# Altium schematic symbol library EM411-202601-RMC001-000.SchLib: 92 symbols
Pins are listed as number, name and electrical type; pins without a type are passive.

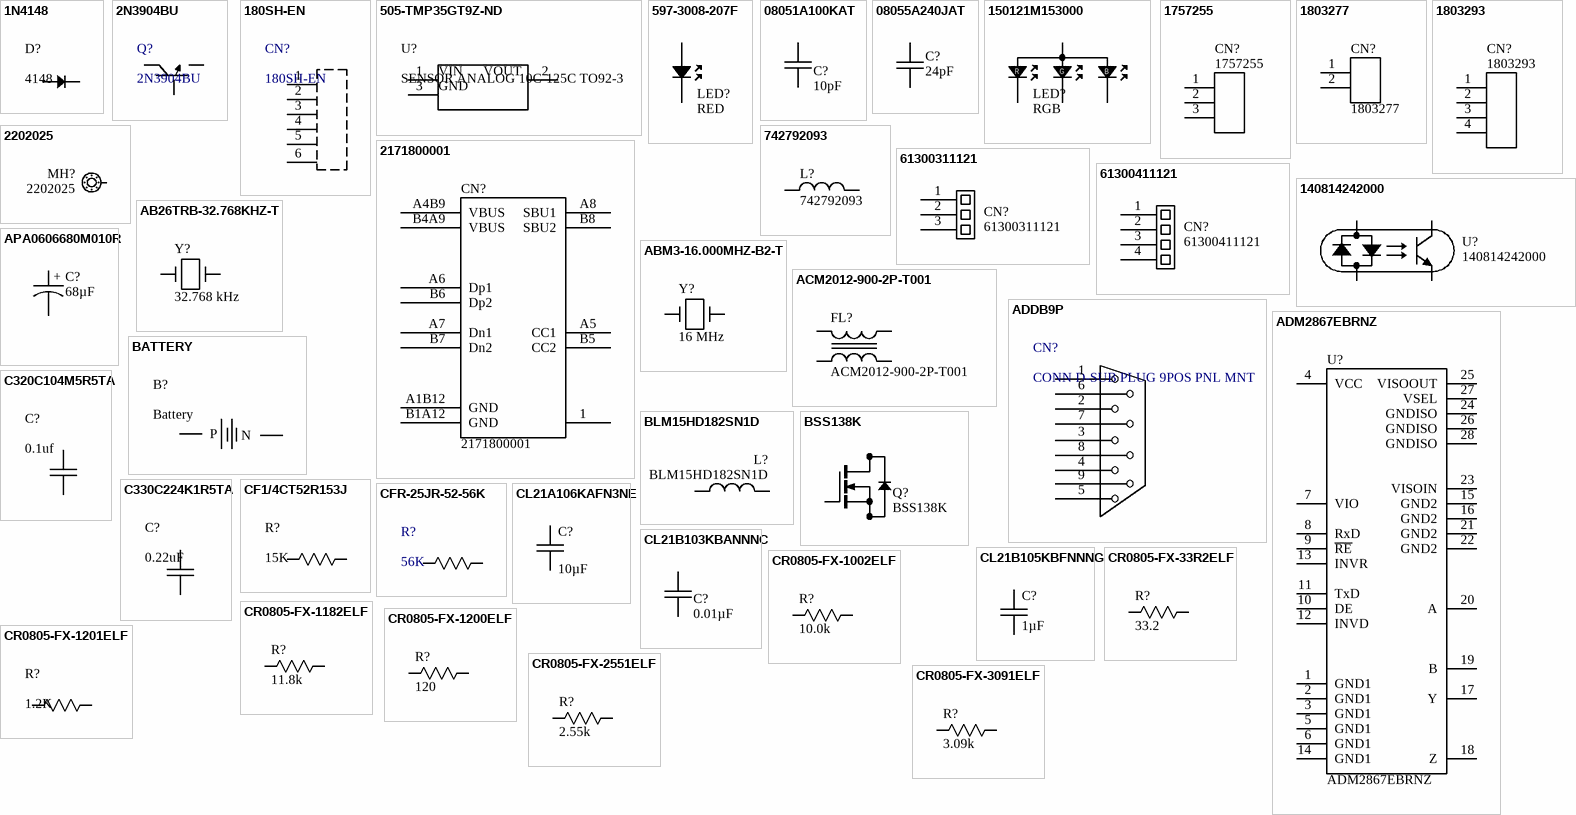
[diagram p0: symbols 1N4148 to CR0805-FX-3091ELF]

## 1N4148
designator D?, comment 4148
Diode 100 V 200mA Through Hole DO-35
footprint LED
pins: 1 A, 2 C

## 2N3904BU
designator Q?
Bipolar (BJT) Transistor NPN 40 V 200 mA 300MHz 625 mW Through Hole TO-92-3
pins: 1, 2, 3

## 180SH-EN
designator CN?
pins: 1, 2 3, 3 5, 4 7, 5 9, 6 9

## 505-TMP35GT9Z-ND
designator U?, comment SENSOR ANALOG 10C-125C TO92-3
Temperature Sensor Analog, Local 10°C ~ 125°C 10mV/°C TO-92-3
pins: 1, 2, 3

## 597-3008-207F
designator LED?, comment RED
Micro LED, 597 Series, Red, SMD LED; PartNumber: 597-3008-207F; Manufacturer: Dialight Corporation
footprint LEDM3228X19N (Molded LED, 2-Leads, Body 3.20x2.80mm, IPC Medium Density)
pins: A, K

## 08051A100KAT
designator C?, comment 10pF
10pF/100V/±10% C0G (NP0) Ceramic Chip Capacitor; Manufacturer: Kyocera/AVX; PartNumber: 08051A100KAT
footprint CAPC2012X09N (Chip Capacitor, 2-Leads, Body 2.00x1.25mm, IPC Medium Density)
pins: 1, 2
1 alternate drawing of the same symbol

## 08055A240JAT
designator C?, comment 24pF
24pF/50V/±5% C0G (NP0) Ceramic Chip Capacitor; Manufacturer: Kyocera/AVX; PartNumber: 08055A240JAT
footprint CAPC2012X09N (Chip Capacitor, 2-Leads, Body 2.00x1.25mm, IPC Medium Density)
pins: 1, 2
1 alternate drawing of the same symbol

## 150121M153000
designator LED?, comment RGB
Micro RGB SMD LED, Common Anode; PartNumber: 150121M153000; Manufacturer: Wurth Elektronik
footprint WURTH_150121M153000
pins: 1 R, 2 G, 3 B, 4 A

## 1757255
designator CN?
MSTBA 2,5/3-G-5,08 Pluggable Terminal Block 3 Pos 5.08mm pitch Through Hole Header; Manufacturer: Phoenix Contact
footprint PHOENIX_1757255 (PCB header - MSTBA 2,5/ 3-G-5,08)
pins: 1, 2, 3

## 1803277
designator CN?
MC 1,5/2G-3,81 Pluggable Terminal Block 2 Pos 3.81mm pitch Through Hole Header; Manufacturer: Phoenix Contact
footprint PHOENIX_1803277 (PCB Header - MC 1,5/ 2-G-3,81)
pins: 1, 2

## 1803293
designator CN?
MC 1,5/4G-3,81 Pluggable Terminal Block 4 Pos 3.81mm pitch Through Hole Header; Manufacturer: Phoenix Contact
footprint PHOENIX_1803293 (PCB header - MC 1,5/ 4-G-3,81)
pins: 1, 2, 3, 4
1 alternate drawing of the same symbol

## 2202025
designator MH?
UM-BASIC/PRO PE CONTACT L1; Manufacturer: Phoenix Contact
footprint PHOENIX_2202025 (PE Contact Level 1)
pins: 0

## 742792093
designator L?
Multilayer SMD Ferrite; Manufacturer: Wurth Elektronik
footprint INDC2012X11N (Chip Inductor, 2-Leads, Body 2.00x1.20mm, IPC Medium Density)
pins: 1, 2

## 2171800001
designator CN?
USB-C Receptacle, Right-Angle, Surface Mount, Top Mount, Center Height 5.9mm, Single Row, 16 Circuits; Manufacturer: Molex
footprint MOLEX_2171800001
pins: 1 SHELL, A1B12 GND, A4B9 VBUS, A5 CC1, A6 Dp1, A7 Dn1, A8 SBU1, B1A12 GND, B4A9 VBUS, B5 CC2, B6 Dp2, B7 Dn2, B8 SBU2

## 61300311121
designator CN?
Connector Header Through Hole 3 position 0.100" (2.54mm); Manufacturer: Wurth Elektronik
footprint WURTH_61300311121
pins: 1, 2, 3
3 alternate drawings of the same symbol

## 61300411121
designator CN?
Connector Header Through Hole 4 position 0.100" (2.54mm); Manufacturer: Wurth Elektronik
footprint WURTH_61300411121
pins: 1, 2, 3, 4
2 alternate drawings of the same symbol

## 140814242000
designator U?
WL-OCPT Optocoupler Phototransistor; Manufacturer: Wurth Elektronik
footprint WURTH_140814242000 (Optocoupler Phototransistor, body 6.5x4.58mm)
pins: 1 A, 2 K, 3 E, 4 C

## AB26TRB-32.768KHZ-T
designator Y?, comment 32.768 kHz
32.768 kHz Radial Can Crystal; PartNumber: AB26TRB-32.768KHZ-T; Manufacturer: Abracon Corporation
footprint ABRACON_AB26TRB (Low Frequency Reflowable Cylindrical Watch Crystal)
pins: 1, 2

## ABM3-16.000MHZ-B2-T
designator Y?, comment 16 MHz
16 MHz Miniature Ceramic SMD Crystal; PartNumber: ABM3-16.000MHZ-B2-T; Manufacturer: Abracon Corporation
footprint ABRACON_ABM3 (Ceramic SMD Crystal)
pins: 1, 2

## ACM2012-900-2P-T001
designator FL?
Common Mode Filter; Manufacturer: TDK
footprint LITTELFUSE_ACM2012-900-2P-T001 (Common Mode Choke)
pins: 1, 2, 3, 4

## ADDB9P
designator CN?, comment CONN D-SUB PLUG 9POS PNL MNT
9 Position D-Sub Plug, Male Pins Connector
pins: 1, 2, 3 1, 4 1, 5 1, 6 1, 7 1, 8 1, 9 1

## ADM2867EBRNZ
designator U?
5.7 kV RMS Signal and Power Isolated RS-485 Transceiver with ±15 kV IEC ESD; Manufacturer: Analog Devices, Inc.
footprint SOP65P1030X265-28N (SOP, 28-Leads, Body 10.30x7.50mm, Pitch 0.65mm, IPC Medium Density)
pins: 1 GND1 (power), 2 GND1 (power), 3 GND1 (power), 4 VCC, 5 GND1 (power), 6 GND1 (power), 7 VIO, 8 RxD, 9 ~{RE}, 10 DE, 11 TxD, 12 INVD, 13 INVR, 14 GND1 (power), 15 GND2, 16 GND2, 17 Y, 18 Z, 19 B, 20 A, 21 GND2, 22 GND2, 23 VISOIN, 24 GNDISO, 25 VISOOUT, 26 GNDISO, 27 VSEL, 28 GNDISO

## APA0606680M010R
designator C?, comment 68µF
68µF/10V/20% SMD Aluminum Conductive Polymer Electrolytic Capacitor; Manufacturer: AVX; PartNumber: APA0606680M010R
footprint CAPAE7366X65M (Aluminum Electrolytic Capacitor, Body 6.60x6.60x6.50mm, IPC Low Density)
pins: 1, 2

## BATTERY
designator B?, comment Battery
pins: 1 P, 2 N

## BLM15HD182SN1D
designator L?
GHz Noise Suppression Chip Ferrite Bead; Manufacturer: Murata Electronics
footprint INDC1005X06N (Chip Inductor, 2-Leads, Body 1.00x0.50mm, IPC Medium Density)
pins: 1, 2

## BSS138K
designator Q?
N-Channel Logic Level Enhancement Mode Field Effect Transistor; Manufacturer: Onsemi
footprint SOT95P237X111-3N (SOT23, 3-Leads, Body 2.92x2.37mm, Pitch 0.95mm, IPC Medium Density)
pins: 1 G "Gate", 2 S "Source", 3 D "Drain"

## C320C104M5R5TA
designator C?, comment 0.1uf
0.1 µF ±20% 50V Ceramic Capacitor X7R Radial
pins: 1, 2

## C330C224K1R5TA
designator C?, comment 0.22uF
0.22 µF ±10% 100V Ceramic Capacitor X7R Radial
footprint C330C224K1R5TA (0.22 µF ±10% 100V Ceramic Capacitor X7R Radial)
pins: 1, 2

## CF1/4CT52R153J
designator R?, comment 15K
15 kOhms ±5% 0.25W, 1/4W Through Hole Resistor Axial Carbon Film
pins: 1, 2

## CFR-25JR-52-56K
designator R?, comment 56K
56 kOhms ±5% 0.25W, 1/4W Through Hole Resistor Axial Automotive AEC-Q200 Carbon Film
pins: 1, 2

## CL21A106KAFN3NE
designator C?, comment 10µF
10µF/25V 10% X5R Multi-Layer Ceramic Capacitor; Manufacturer: Samsung Electro-Mechanics; PartNumber: CL21A106KAFN3NE
footprint CAPC2012X14N (Chip Capacitor, 2-Leads, Body 2.00x1.25mm, IPC Medium Density)
pins: 1, 2

## CL21B103KBANNNC
designator C?, comment 0.01µF
0.01µF/50V/±10% X7R Ceramic Chip Capacitor; Manufacturer: Samsung Electro-Mechanics; PartNumber: CL21B103KBANNNC
footprint CAPC2012X08N (Chip Capacitor, 2-Leads, Body 2.00x1.25mm, IPC Medium Density)
pins: 1, 2
1 alternate drawing of the same symbol

## CL21B105KBFNNNG
designator C?, comment 1µF
1µF/50V/±10% X7R Ceramic Chip Capacitor; Manufacturer: Samsung Electro-Mechanics; PartNumber: CL21B105KBFNNNG
footprint CAPC2012X14N (Chip Capacitor, 2-Leads, Body 2.00x1.25mm, IPC Medium Density)
pins: 1, 2
1 alternate drawing of the same symbol

## CR0805-FX-33R2ELF
designator R?, comment 33.2
33.2, 1%, 0.125W Thick Film Chip Resistor; Manufacturer: Bourns; PartNumber: CR0805-FX-33R2ELF
footprint RESC2012X06N (Chip Resistor, 2-Leads, Body 2.00x1.25mm, IPC Medium Density)
pins: 1, 2

## CR0805-FX-1002ELF
designator R?, comment 10.0k
10.0k, 1%, 0.125W Thick Film Chip Resistor; Manufacturer: Bourns; PartNumber: CR0805-FX-1002ELF
footprint RESC2012X06N (Chip Resistor, 2-Leads, Body 2.00x1.25mm, IPC Medium Density)
pins: 1, 2

## CR0805-FX-1182ELF
designator R?, comment 11.8k
11.8k, 1%, 0.125W Thick Film Chip Resistor; Manufacturer: Bourns; PartNumber: CR0805-FX-1182ELF
footprint RESC2012X06N (Chip Resistor, 2-Leads, Body 2.00x1.25mm, IPC Medium Density)
pins: 1, 2

## CR0805-FX-1200ELF
designator R?, comment 120
120, 1%, 0.125W Thick Film Chip Resistor; Manufacturer: Bourns; PartNumber: CR0805-FX-1200ELF
footprint RESC2012X06N (Chip Resistor, 2-Leads, Body 2.00x1.25mm, IPC Medium Density)
pins: 1, 2

## CR0805-FX-1201ELF
designator R?, comment 1.2K
1.2 kOhms ±1% 0.125W, 1/8W Chip Resistor 0805 (2012 Metric) Moisture Resistant Thick Film
footprint RESC2012X06N (Chip Resistor, 2-Leads, Body 2.00x1.25mm, IPC Medium Density)
pins: 1, 2

## CR0805-FX-2551ELF
designator R?, comment 2.55k
2.55k, 1%, 0.125W Thick Film Chip Resistor; Manufacturer: Bourns; PartNumber: CR0805-FX-2551ELF
footprint RESC2012X06N (Chip Resistor, 2-Leads, Body 2.00x1.25mm, IPC Medium Density)
pins: 1, 2

## CR0805-FX-3091ELF
designator R?, comment 3.09k
3.09k, 1%, 0.125W Thick Film Chip Resistor; Manufacturer: Bourns; PartNumber: CR0805-FX-3091ELF
footprint RESC2012X06N (Chip Resistor, 2-Leads, Body 2.00x1.25mm, IPC Medium Density)
pins: 1, 2

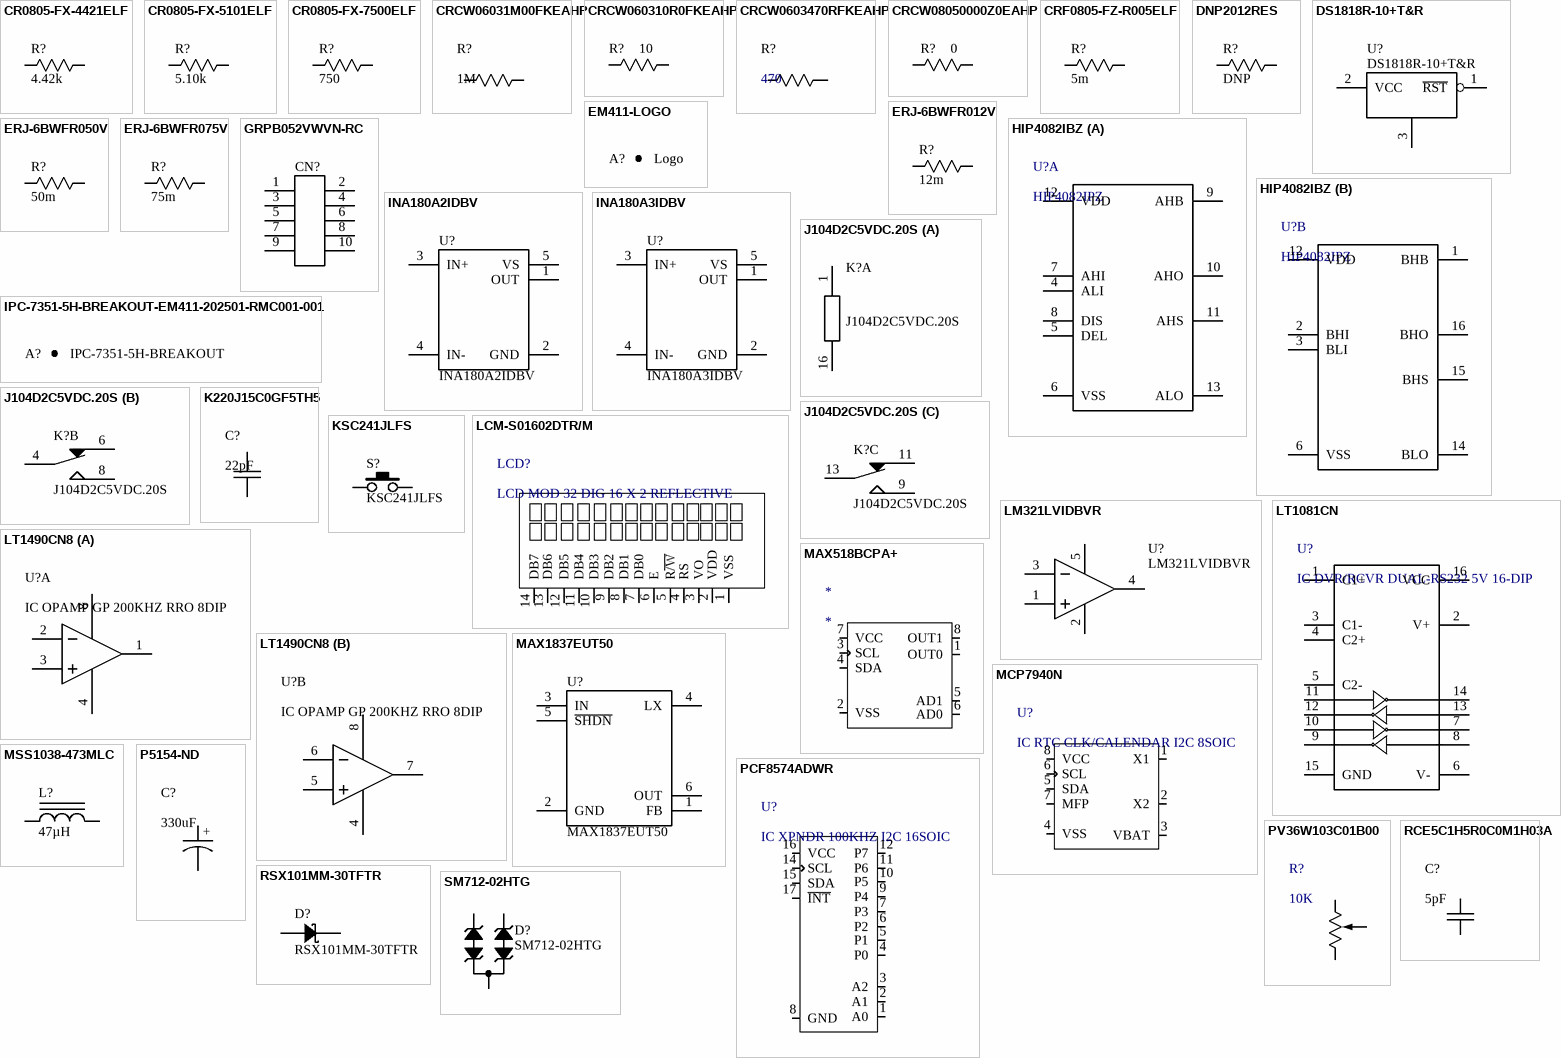
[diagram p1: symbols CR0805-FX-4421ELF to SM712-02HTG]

## CR0805-FX-4421ELF
designator R?, comment 4.42k
4.42k, 1%, 0.125W Thick Film Chip Resistor; Manufacturer: Bourns; PartNumber: CR0805-FX-4421ELF
footprint RESC2012X06N (Chip Resistor, 2-Leads, Body 2.00x1.25mm, IPC Medium Density)
pins: 1, 2

## CR0805-FX-5101ELF
designator R?, comment 5.10k
5.10k, 1%, 0.125W Thick Film Chip Resistor; Manufacturer: Bourns; PartNumber: CR0805-FX-5101ELF
footprint RESC2012X06N (Chip Resistor, 2-Leads, Body 2.00x1.25mm, IPC Medium Density)
pins: 1, 2

## CR0805-FX-7500ELF
designator R?, comment 750
750, 1%, 0.125W Thick Film Chip Resistor; Manufacturer: Bourns; PartNumber: CR0805-FX-7500ELF
footprint RESC2012X06N (Chip Resistor, 2-Leads, Body 2.00x1.25mm, IPC Medium Density)
pins: 1, 2

## CRCW06031M00FKEAHP
designator R?, comment 1M
1 MOhms ±1% 0.333W, 1/3W Chip Resistor 0603 (1608 Metric) Automotive AEC-Q200, Pulse Withstanding Thick Film
pins: 1, 2

## CRCW060310R0FKEAHP
designator R?, comment 10
10, 1%, 0.33W Pulse Proof, High Power Thick Film Chip Resistor; Manufacturer: Vishay Intertechnology; PartNumber: CRCW060310R0FKEAHP
footprint RESC1608X06N (Chip Resistor, 2-Leads, Body 1.60x0.85mm, IPC Medium Density)
pins: 1, 2

## CRCW0603470RFKEAHP
designator R?, comment 470
470 Ohms ±1% 0.333W, 1/3W Chip Resistor 0603 (1608 Metric) Automotive AEC-Q200, Pulse Withstanding Thick Film
pins: 1, 2

## CRCW08050000Z0EAHP
designator R?, comment 0
0, Jumper, Pulse Proof, High Power Thick Film Chip Resistor; Manufacturer: Vishay Intertechnology; PartNumber: CRCW08050000Z0EAHP
footprint VISHAY_RESC2012X06N (Chip Resistor, 2-Leads, Body 2.00x1.25mm, IPC Medium Density)
pins: 1, 2

## CRF0805-FZ-R005ELF
designator R?, comment 5m
5m, 1%, 0.5W Thick Film Chip Resistor; Manufacturer: Bourns; PartNumber: CRF0805-FZ-R005ELF
footprint RESC2012X08N (Chip Resistor, 2-Leads, Body 2.00x1.25mm, IPC Medium Density)
pins: 1, 2

## DNP2012RES
designator R?, comment DNP  (no BOM)
Placeholder for 2012 Resistor; Manufacturer: Confederation College; PartNumber: DNP2012RES
footprint RESC2012X06N (Chip Resistor, 2-Leads, Body 2.00x1.25mm, IPC Medium Density)
pins: 1, 2

## DS1818R-10+T&R
designator U?
3.3 V EconoReset with Pushbutton; Manufacturer: Maxim Integrated
footprint SOT95P237X112-3N (SOT23, 3-Leads, Body 2.92x2.37mm, Pitch 0.95mm, IPC Medium Density)
pins: 1 ~{RST} (oc), 2 VCC (power), 3 GND (power)

## EM411-LOGO
designator A?, comment Logo  (no BOM)
footprint EM411-LOGO (Confederation College Logo)

## ERJ-6BWFR012V
designator R?, comment 12m
12m, 1%, 0.5W Thick Film Chip Resistor; Manufacturer: Panasonic; PartNumber: ERJ-6BWFR012V
footprint RESC2012X08N (Chip Resistor, 2-Leads, Body 2.00x1.25mm, IPC Medium Density)
pins: 1, 2

## ERJ-6BWFR050V
designator R?, comment 50m
50m, 1%, 0.5W Thick Film Chip Resistor; Manufacturer: Panasonic; PartNumber: ERJ-6BWFR050V
footprint RESC2012X08N (Chip Resistor, 2-Leads, Body 2.00x1.25mm, IPC Medium Density)
pins: 1, 2

## ERJ-6BWFR075V
designator R?, comment 75m
75m, 1%, 0.5W Thick Film Chip Resistor; Manufacturer: Panasonic; PartNumber: ERJ-6BWFR075V
footprint RESC2012X08N (Chip Resistor, 2-Leads, Body 2.00x1.25mm, IPC Medium Density)
pins: 1, 2

## GRPB052VWVN-RC
designator CN?  (value not drawn)
.050"[1.27mm] Contact Centers, Male Header; Manufacturer: Sullins Connector Solutions, Inc.
footprint SULLINS_GRPB052VWVN-RC (CONN HEADER VERT 10POS 1.27MM)
pins: 1, 2, 3, 4, 5, 6, 7, 8, 9, 10

## HIP4082IBZ
designator U?, comment HIP4082IPZ
Half Bridge, Full Bridge Driver DC Motors, General Purpose N-Channel MOSFET 16-SOIC
part A pins: 4 ALI, 5 DEL, 6 VSS, 7 AHI, 8 DIS, 9 AHB, 10 AHO, 11 AHS, 12 VDD, 13 ALO
part B pins: 1 BHB, 2 BHI, 3 BLI, 6 VSS, 12 VDD, 14 BLO, 15 BHS, 16 BHO

## INA180A2IDBV
designator U?
Voltage Output, Current-Sense Amplifiers, Gain 50; Manufacturer: Texas Instruments
footprint SOT95P280X145-5N (SOT23, 5-Leads, Body 2.90x2.80mm, Pitch 0.95mm, IPC Medium Density)
pins: 1 OUT, 2 GND, 3 IN+, 4 IN-, 5 VS

## INA180A3IDBV
designator U?
Voltage Output, Current-Sense Amplifiers, Gain 100; Manufacturer: Texas Instruments
footprint SOT95P280X145-5N (SOT23, 5-Leads, Body 2.90x2.80mm, Pitch 0.95mm, IPC Medium Density)
pins: 1 OUT, 2 GND, 3 IN+, 4 IN-, 5 VS

## IPC-7351-5H-BREAKOUT-EM411-202501-RMC001-001
designator A?, comment IPC-7351-5H-BREAKOUT  (no BOM)
IPC-7351-5H-BREAKOUT for EM411-202501-RMC001-001
footprint IPC-7351-5H-BREAKOUT-EM411-202501-RMC001-001 (IPC-7351 Breakout for EM411-202401-RMC001-001)

## J104D2C5VDC.20S
designator K?
J104D Series Dual Form C 5V, 2A PCB Relay; Manufacturer: Circuit Interrupter Technology
footprint CIT_J104D (Dual Form C Signal Relay)
part A pins: 1, 16
part B pins: 4, 6, 8
part C pins: 9, 11, 13
1 alternate drawing of the same symbol

## K220J15C0GF5TH5
designator C?, comment 22pF
22 pF ±5% 50V Ceramic Capacitor C0G, NP0 Radial
footprint K220J15C0GF5TH5
pins: 1, 2

## KSC241JLFS
designator S?
KSC Series Sealed Tact Switch for SMT; Manufacturer: C&K Components
footprint CK_KSC241JLFS (KSC2 Series Sealed Tact Switch for SMT)
pins: 1, 2

## LCM-S01602DTR/M
designator LCD?, comment LCD MOD 32 DIG 16 X 2 REFLECTIVE
Character Display Module Reflective 5 x 8 Dots TN - Twisted Nematic Without Backlight Parallel 66.00mm x 26.00mm x 6.50mm
pins: 1 VSS, 2 VDD, 3 VO, 4 RS, 5 R~{/W}, 6 E, 7 DB0, 8 DB1, 9 DB2, 10 DB3, 11 DB4, 12 DB5, 13 DB6, 14 DB7

## LM321LVIDBVR
designator U?
Industry Standard, Low Voltage Operational Amplifier; Manufacturer: Texas Instruments
footprint SOT95P280X145-5N (SOT23, 5-Leads, Body 2.90x2.80mm, Pitch 0.95mm, IPC Medium Density)
pins: 1 IN+, 2 V- (power), 3 IN-, 4 OUT, 5 V+ (power)

## LT1081CN
designator U?, comment IC DVR/RCVR DUAL-RS232 5V 16-DIP
2/2 Transceiver Full RS232 16-PDIP
pins: 1 C1+, 2 V+, 3 C1-, 4 C2+, 5 C2-, 6 V-, 7 C2-, 8 C2-, 9 C2-, 10 C2-, 11 C2-, 12 C2-, 13 C2-, 14 C2-, 15 GND, 16 VCC

## LT1490CN8
designator U?, comment IC OPAMP GP 200KHZ RRO 8DIP
Standard (General Purpose) Amplifier 2 Circuit Rail-to-Rail 8-PDIP
part A pins: 1 9, 2 IN-, 3 IN+, 4 V- (power), 8 V+ (power)
part B pins: 4 V- (power), 5 IN+, 6 IN-, 7, 8 V+ (power)

## MAX518BCPA+
designator *
pins: 1 OUT0, 2 VSS, 3 SCL, 4 SDA, 5 AD1, 6 AD0, 7 VCC, 8 OUT1

## MAX1837EUT50
designator U?
24V Internal Switch, 100% Duty Cycle, Step-Down Converter; Manufacturer: Maxim Integrated
footprint SOT95P280X145-6N (SOT23, 6-Leads, Body 2.90x2.80mm, Pitch 0.95mm, IPC Medium Density)
pins: 1 FB, 2 GND, 3 IN, 4 LX, 5 ~{SHDN}, 6 OUT

## MCP7940N
designator U?, comment IC RTC CLK/CALENDAR I2C 8SOIC
Real Time Clock (RTC) IC Clock/Calendar 64B I2C, 2-Wire Serial 8-SOIC (0.154", 3.90mm Width)
pins: 1 X1, 2 X2, 3 VBAT, 4 VSS, 5 SDA, 6 SCL, 7 MFP, 8 VCC

## MSS1038-473MLC
designator L?, comment 47µH
47µH Shielded Power Inductor; PartNumber: MSS1038-473MLC; Manufacturer: Coilcraft
footprint INDP102102X40N (Precision Wire Wound Inductor, 2-Leads, Body 10.20x10.15mm, IPC Medium Density)
pins: 1, 2

## P5154-ND
designator C?, comment 330uF
330 µF 25 V Aluminum Electrolytic Capacitors Radial, Can 2000 Hrs @ 85°C
footprint PCAP_8x112_PAN
pins: 1, 2

## PCF8574ADWR
designator U?, comment IC XPNDR 100KHZ I2C 16SOIC
I/O Expander 8 I2C 100 kHz 16-SOIC
pins: 1 A0, 2 A1, 3 A2, 4 P0, 5 P1, 6 P2, 7 P3, 8 GND, 9 P4, 10 P5, 11 P6, 12 P7, 14 SCL, 15 SDA, 16 VCC, 17 ~{INT}

## PV36W103C01B00
designator R?, comment 10K
10 kOhms 0.5W, 1/2W PC Pins Through Hole Trimmer Potentiometer Cermet 25 Turn Top Adjustment
pins: 1, 2, 3

## RCE5C1H5R0C0M1H03A
designator C?, comment 5pF
5 pF ±0.25pF 50V Ceramic Capacitor C0G, NP0 Radial
footprint RCE5C1H5R0C0M1H03A (5 pF ±0.25pF 50V Ceramic Capacitor C0G, NP0 Radial)
pins: 1, 2

## RSX101MM-30TFTR
designator D?
Schottky Barrier Diode; Manufacturer: Rohm Semiconductor
footprint SODFL350X90-2N (SODFL, 2-Leads, Body 1.60x3.50mm, IPC Medium Density)
pins: A, K

## SM712-02HTG
designator D?
SM712 Series 600W Asymmetrical TVS Diode Array; Manufacturer: Littelfuse
footprint SOT95P237X112-3N (SOT23, 3-Leads, Body 2.92x2.37mm, Pitch 0.95mm, IPC Medium Density)
pins: 1, 2, 3

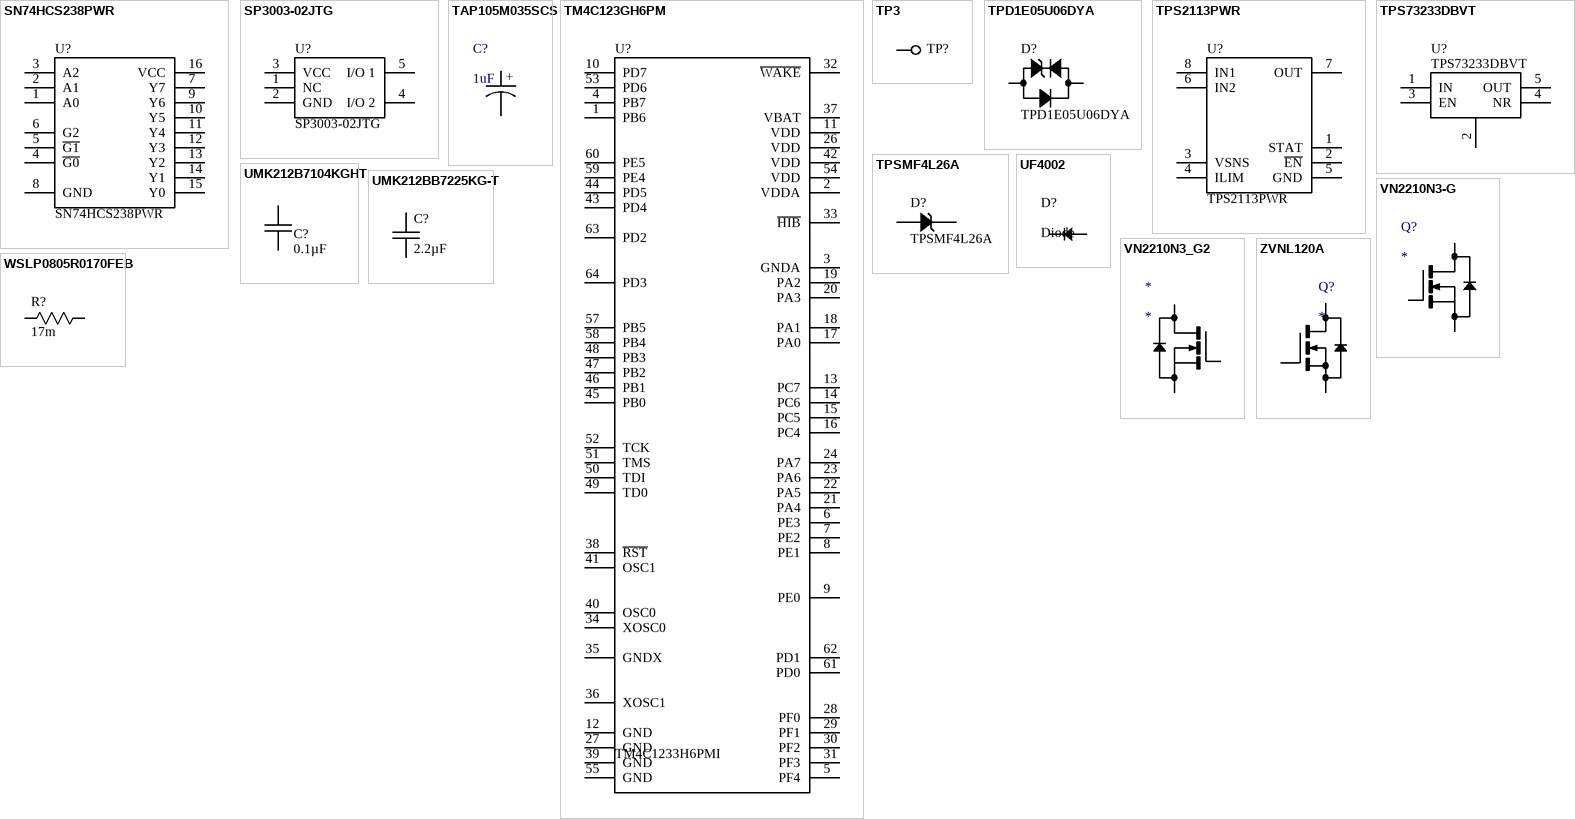
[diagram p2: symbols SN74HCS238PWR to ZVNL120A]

## SN74HCS238PWR
designator U?
3-to 8-Line Decoder/Demultiplexer with Schmitt-Trigger Inputs; Manufacturer: Texas Instruments
footprint TSOP65P640X120-16N (TSOP, 16-Leads, Body 5.00x4.40mm, Pitch 0.65mm, IPC Medium Density)
pins: 1 A0, 2 A1, 3 A2, 4 ~{G0}, 5 ~{G1}, 6 G2, 7 Y7, 8 GND, 9 Y6, 10 Y5, 11 Y4, 12 Y3, 13 Y2, 14 Y1, 15 Y0, 16 VCC

## SP3003-02JTG
designator U?
TVS Diode Array - Low Capacitance ESD Protection; Manufacturer: Littelfuse
footprint SOT65P220X90-5N (SOT,0.65mm pitch;5 pin, 1.25mm W X 2.05mm L X 0.95mm H body)
footprint SOT65P220X110-5N (SOT23, 5-Leads, Body 2.05x2.20mm, Pitch 0.65mm, IPC Medium Density)
pins: 1 NC, 2 GND, 3 VCC, 4 I/O 2, 5 I/O 1

## TAP105M035SCS
designator C?, comment 1uF
1 µF Conformal Coated Tantalum Capacitors 35 V Radial 8Ohm
footprint TAP105M035SCS
pins: 1, 2

## TM4C123GH6PM
designator U?, comment TM4C1233H6PMI
Microcontroller; Manufacturer: Texas Instruments
footprint TSQFP50P1200X1200X160-64N (TSQFP, 64-Leads, Body 10.00x10.00mm, Pitch 0.50mm, IPC Medium Density)
pins: 1 PB6, 2 VDDA (power), 3 GNDA, 4 PB7, 5 PF4, 6 PE3, 7 PE2, 8 PE1, 9 PE0, 10 PD7, 11 VDD (power), 12 GND (power), 13 PC7, 14 PC6, 15 PC5, 16 PC4, 17 PA0, 18 PA1, 19 PA2, 20 PA3, 21 PA4, 22 PA5, 23 PA6, 24 PA7, 26 VDD, 27 GND, 28 PF0, 29 PF1, 30 PF2, 31 PF3, 32 ~{WAKE}, 33 ~{HIB}, 34 XOSC0, 35 GNDX (power), 36 XOSC1, 37 VBAT, 38 ~{RST}, 39 GND (power), 40 OSC0 (power), 41 OSC1 (power), 42 VDD, 43 PD4, 44 PD5, 45 PB0, 46 PB1, 47 PB2, 48 PB3, 49 TD0 (power), 50 TDI, 51 TMS (power), 52 TCK, 53 PD6, 54 VDD (power), 55 GND (power), 57 PB5, 58 PB4, 59 PE4, 60 PE5, 61 PD0, 62 PD1, 63 PD2, 64 PD3
2 alternate drawings of the same symbol

## TP3
designator TP?, comment Test Point  (value not drawn)  (no BOM)
Test Point, Surface Mount, 3 mm; Manufacturer: Confederation College
footprint TP100 (Surface Mount Test Point)
pins: 1

## TPD1E05U06DYA
designator D?
Single-Channel ESD Protection Diode; Manufacturer: Texas Instruments
footprint SODFL160X77-2N (SODFL, 2-Leads, Body 0.80x1.60mm, IPC Medium Density)
pins: A, K

## TPS2113PWR
designator U?
Autoswitching Power Mux; Manufacturer: Texas Instruments
footprint TSOP65P640X120-8N (TSOP, 8-Leads, Body 3.00x4.40mm, Pitch 0.65mm, IPC Medium Density)
pins: 1 STAT, 2 ~{EN}, 3 VSNS, 4 ILIM, 5 GND, 6 IN2, 7 OUT, 8 IN1

## TPS73233DBVT
designator U?
250 mA, 3.3V Low Dropout Voltage Regulator; Manufacturer: Texas Instruments
footprint SOT95P280X145-5N (SOT23, 5-Leads, Body 2.90x2.80mm, Pitch 0.95mm, IPC Medium Density)
pins: 1 IN "Input", 2 GND "Ground", 3 EN "Enable", 4 NR "Noise Reduction", 5 OUT "Output"

## TPSMF4L26A
designator D?
TVS Diode; Manufacturer: Littelfuse
footprint SODFL370X108-2N (SODFL, 2-Leads, Body 1.85x3.70mm, IPC Medium Density)
pins: A, K

## UF4002
designator D?, comment Diode
Diode 100 V 1A Through Hole DO-41
footprint UF4002 (Diode 100 V 1A Through Hole DO-41)
pins: A Anode, K Cathode

## UMK212B7104KGHT
designator C?, comment 0.1µF
0.1µF/50V/±10% X7R Ceramic Chip Capacitor; Manufacturer: Taiyo Yuden; PartNumber: UMK212B7104KGHT
footprint CAPC2012X14N (Chip Capacitor, 2-Leads, Body 2.00x1.25mm, IPC Medium Density)
pins: 1, 2

## UMK212BB7225KG-T
designator C?, comment 2.2µF
2.2µF/50V/10% Multilayer Ceramic Chip Capacitor; Manufacturer: Taiyo Yuden; PartNumber: UMK212BB7225KG-T
footprint CAPC2012X14N (Chip Capacitor, 2-Leads, Body 2.00x1.25mm, IPC Medium Density)
pins: 1, 2

## VN2210N3-G
designator Q?
N-Channel 100 V 23A (Tc) 45W (Tc) Surface Mount PowerPAK® SO-8
pins: 1 S "Drain", 2 G "Gate", 3 D "Drain"

## VN2210N3_G2
designator *
pins: 1 S "Drain", 2 G "Gate", 3 D "Drain"

## WSLP0805R0170FEB
designator R?, comment 17m
17m, 1%, 0.5W Thick Film Chip Resistor; Manufacturer: Vishay Dale; PartNumber: WSLP0805R0170FEB
footprint RESC2013X05N (Chip Resistor, 2-Leads, Body 2.03x1.32mm, IPC Medium Density)
pins: 1, 2

## ZVNL120A
designator Q?
N-Channel 200 V 180mA (Ta) 700mW (Ta) Through Hole TO-92
footprint ZVNL120A
pins: 1 S, 2 G "Gate", 3 D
